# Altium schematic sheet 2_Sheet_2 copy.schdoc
size 302 x 215 mm; Name: A_A4; Symbol: A_A4; Device: A_A4; @Project Name: Quectel_EC200U_Board; REV: 1.1; Date: 11-07-24; Sheet: 1/1; Draw By: Anusha; Company: FervidSmart Solutions; Convert to PCB: yes; Add into BOM: yes; @Page No: 2; @Page Count: 3; @Schematic Name: Quectel_EC200U with BuckBoost Board; @Board Name: Quectel_EC200U with BuckBoost Board; @Update Date: 2025-06-21; @Create Time: 12:09:23; @Update Time: 16:36:11; @Page Name: Sheet_2 copy; @Create Date: 2025-06-19
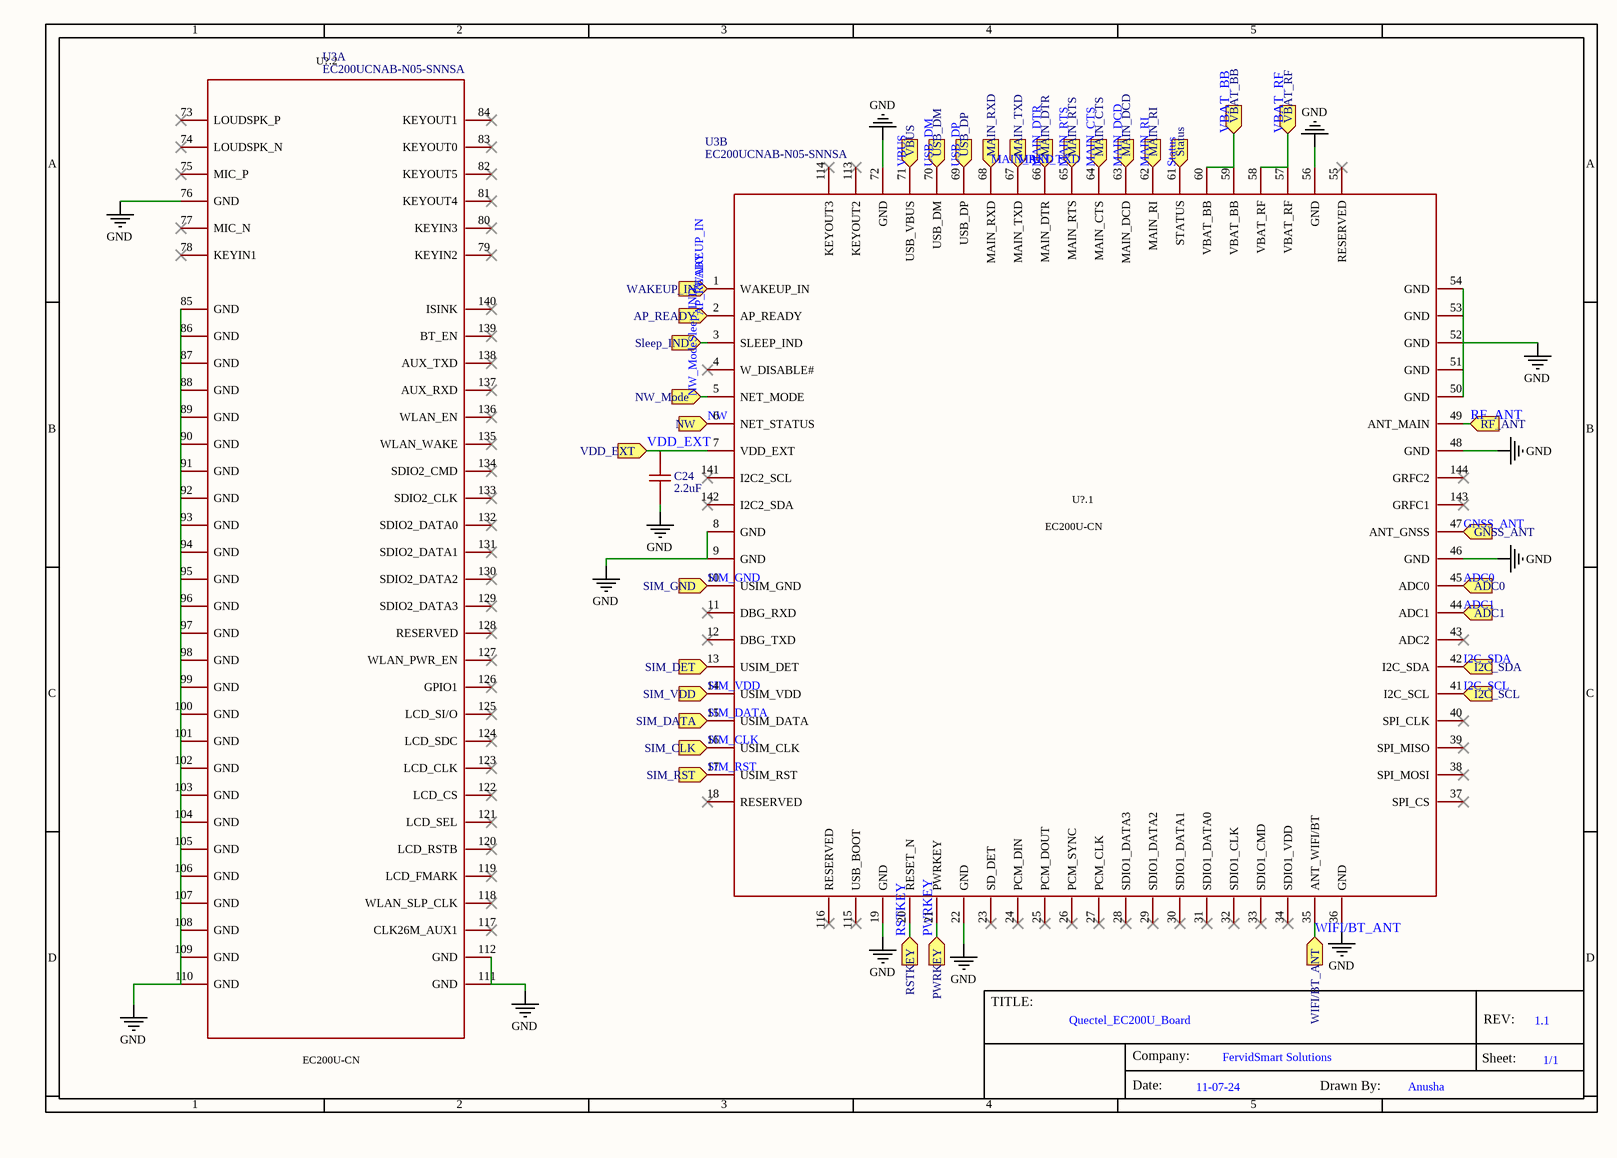
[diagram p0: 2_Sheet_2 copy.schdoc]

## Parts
C24  2.2uF  [C0603]
U3  EC200UCNAB-N05-SNNSA  [LCC-LGA-144_L32.0-W29.0-CAT1-CUIOT-MZ-6]  (parts A,B of 2)

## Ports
ADC0 (in), ADC1 (in), AP_READY (in), GNSS_ANT (in), I2C_SCL (in), I2C_SDA (in), MAIN_CTS (in), MAIN_DCD (in), MAIN_DTR (in), MAIN_RI (in), MAIN_RTS (in), MAIN_RXD (in), MAIN_TXD (in), NW (in), NW_Mode (in), PWRKEY (in), RF_ANT (in), RSTKEY (in), SIM_CLK (in), SIM_DATA (in), SIM_DET (in), SIM_GND (in), SIM_RST (in), SIM_VDD (in), Sleep_IND (in), Status (in), USB_DM (in), USB_DP (in), VBAT_BB (in), VBAT_RF (in), VBUS (in), VDD_EXT (in), WAKEUP_IN (in), WIFI/BT_ANT (in)

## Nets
GND: C24.1 U3.8(GND) U3.9(GND) U3.19(GND) U3.22(GND) U3.36(GND) U3.46(GND) U3.48(GND) U3.50(GND) U3.51(GND) U3.52(GND) U3.53(GND) U3.54(GND) U3.56(GND) U3.72(GND) U3.76(GND) U3.85(GND) U3.86(GND) U3.87(GND) U3.88(GND) U3.89(GND) U3.90(GND) U3.91(GND) U3.92(GND) U3.93(GND) U3.94(GND) U3.95(GND) U3.96(GND) U3.97(GND) U3.98(GND) U3.99(GND) U3.100(GND) U3.101(GND) U3.102(GND) U3.103(GND) U3.104(GND) U3.105(GND) U3.106(GND) U3.107(GND) U3.108(GND) U3.109(GND) U3.110(GND) U3.111(GND) U3.112(GND)
ADC0: U3.45(ADC0) ; port ADC0
ADC1: U3.44(ADC1) ; port ADC1
AP_READY: U3.2(AP_READY) ; port AP_READY
GNSS_ANT: U3.47(ANT_GNSS) ; port GNSS_ANT
I2C_SCL: U3.41(I2C_SCL) ; port I2C_SCL
I2C_SDA: U3.42(I2C_SDA) ; port I2C_SDA
MAIN_CTS: U3.64(MAIN_CTS) ; port MAIN_CTS
MAIN_DCD: U3.63(MAIN_DCD) ; port MAIN_DCD
MAIN_DTR: U3.66(MAIN_DTR) ; port MAIN_DTR
MAIN_RI: U3.62(MAIN_RI) ; port MAIN_RI
MAIN_RTS: U3.65(MAIN_RTS) ; port MAIN_RTS
MAIN_RXD: U3.68(MAIN_RXD) ; port MAIN_RXD
MAIN_TXD: U3.67(MAIN_TXD) ; port MAIN_TXD
NW: U3.6(NET_STATUS) ; port NW
NW_Mode: U3.5(NET_MODE) ; port NW_Mode
PWRKEY: U3.21(PWRKEY) ; port PWRKEY
RF_ANT: U3.49(ANT_MAIN) ; port RF_ANT
RSTKEY: U3.20(RESET_N) ; port RSTKEY
SIM_CLK: U3.16(USIM_CLK) ; port SIM_CLK
SIM_DATA: U3.15(USIM_DATA) ; port SIM_DATA
SIM_DET: U3.13(USIM_DET) ; port SIM_DET
SIM_GND: U3.10(USIM_GND) ; port SIM_GND
SIM_RST: U3.17(USIM_RST) ; port SIM_RST
SIM_VDD: U3.14(USIM_VDD) ; port SIM_VDD
Sleep_IND: U3.3(SLEEP_IND) ; port Sleep_IND
Status: U3.61(STATUS) ; port Status
USB_DM: U3.70(USB_DM) ; port USB_DM
USB_DP: U3.69(USB_DP) ; port USB_DP
VBAT_BB: U3.59(VBAT_BB) U3.60(VBAT_BB) ; port VBAT_BB
VBAT_RF: U3.57(VBAT_RF) U3.58(VBAT_RF) ; port VBAT_RF
VBUS: U3.71(USB_VBUS) ; port VBUS
VDD_EXT: C24.2 U3.7(VDD_EXT) ; port VDD_EXT
WAKEUP_IN: U3.1(WAKEUP_IN) ; port WAKEUP_IN
WIFI/BT_ANT: U3.35(ANT_WIFI/BT) ; port WIFI/BT_ANT

Not connected (* = marked no-connect by the designer): U3 4(W_DISABLE#)* 11(DBG_RXD)* 12(DBG_TXD)* 18(RESERVED)* 23(SD_DET)* 24(PCM_DIN)* 25(PCM_DOUT)* 26(PCM_SYNC)* 27(PCM_CLK)* 28(SDIO1_DATA3)* 29(SDIO1_DATA2)* 30(SDIO1_DATA1)* 31(SDIO1_DATA0)* 32(SDIO1_CLK)* 33(SDIO1_CMD)* 34(SDIO1_VDD)* 37(SPI_CS)* 38(SPI_MOSI)* 39(SPI_MISO)* 40(SPI_CLK)* 43(ADC2)* 55(RESERVED)* 73(LOUDSPK_P)* 74(LOUDSPK_N)* 75(MIC_P)* 77(MIC_N)* 78(KEYIN1)* 79(KEYIN2)* 80(KEYIN3)* 81(KEYOUT4)* 82(KEYOUT5)* 83(KEYOUT0)* 84(KEYOUT1)* 113(KEYOUT2)* 114(KEYOUT3)* 115(USB_BOOT)* 116(RESERVED)* 117(CLK26M_AUX1)* 118(WLAN_SLP_CLK)* 119(LCD_FMARK)* 120(LCD_RSTB)* 121(LCD_SEL)* 122(LCD_CS)* 123(LCD_CLK)* 124(LCD_SDC)* 125(LCD_SI/O)* 126(GPIO1)* 127(WLAN_PWR_EN)* 128(RESERVED)* 129(SDIO2_DATA3)* 130(SDIO2_DATA2)* 131(SDIO2_DATA1)* 132(SDIO2_DATA0)* 133(SDIO2_CLK)* 134(SDIO2_CMD)* 135(WLAN_WAKE)* 136(WLAN_EN)* 137(AUX_RXD)* 138(AUX_TXD)* 139(BT_EN)* 140(ISINK)* 141(I2C2_SCL)* 142(I2C2_SDA)* 143(GRFC1)* 144(GRFC2)*

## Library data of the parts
C24 = CL10A225KO8NNNC: Manufacturer: SAMSUNG(三星); Add into BOM: yes; Tolerance: ±10%; Check: true
U3 = EC200UCNAB-N05-SNNSA: Manufacturer: 移远 Quectel; Convert to PCB: yes; Check: true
